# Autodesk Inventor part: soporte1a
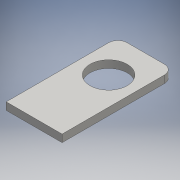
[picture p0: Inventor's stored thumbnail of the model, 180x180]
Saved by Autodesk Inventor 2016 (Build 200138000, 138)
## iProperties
Created: 2016-06
Part Number: soporte1a
Material: Genérico
Document SubType Name: Modeling
Designer: adm
Density: 1 g/cm^3
Appearance: Valor por defecto
Author: adm
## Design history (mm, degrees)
sketch "Boceto1"
  geometry: L1 (-15, -30)-(15, -30); L2 (15, -30)-(15, 30); L3 (15, 30)-(-15, 30); L4 (-15, 30)-(-15, -30); L5 (-15, -30)-(15, 30); L6 (15, -30)-(-15, 30); 1 further point
  constraints: 12 end point, 2 midpoint, 2 parallel, 1 horizontal, 1 perpendicular
  dimensions: "d0" = 30 distance of L3.end L2.end; "d1" = 60 distance of L2.end L1.end
extrude "Extrusión1" new body sketch "Boceto1" distance "d2" = 4; taper "d3" = 0 deg
fillet "Empalme1" dims "d4" = 5
sketch "Boceto2"
  geometry: L1 (10, 30)-(-10, 30) reference; C1 r 10 at (0, 10); 2 further points
  constraints: 1 centre point, 1 coincident
  dimensions: "d5" = 20 distance from line of point (0, 10) L1; "d6" = 20 diameter of C1
extrude "Extrusión2" cut sketch "Boceto2" distance "d7" = 4; taper "d8" = 0 deg
node "Sólido1"
